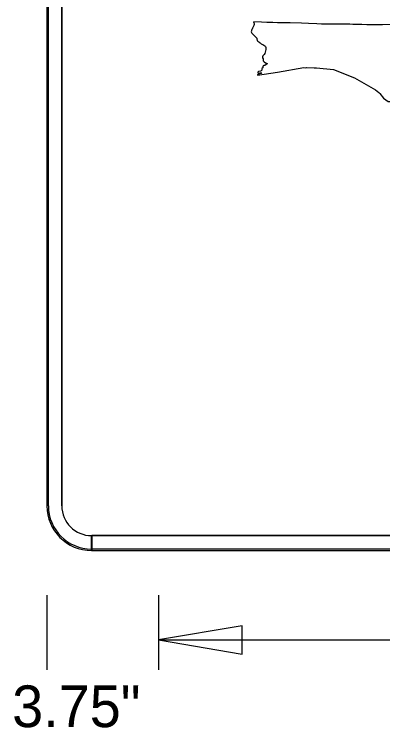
# Model space of a CAD drawing. Extents: x 0 to 770, y 0 to 495.
# Drawn here: x 108.2 to 139.1, y 37.8 to 97.6 of the extents above; entities that cross this region are included whole.
import ezdxf

# ---------------------------------------------------------------- set-up
doc = ezdxf.new("R2010")
doc.units = 0
for name, color, linetype in [('Dimension', 7, 'Continuous'), ('GSBWFill', 7, 'Continuous'), ('GSColorFill', 7, 'Continuous'), ('GSDims', 7, 'Continuous'), ('GSOutline', 7, 'Continuous'), ('SupstrConc', 7, 'Continuous')]:
    doc.layers.add(name, color=color, linetype=linetype)

msp = doc.modelspace()

# ---------------------------------------------------------------- linework, layer by layer
at = {"layer": 'Dimension'}
msp.add_lwpolyline([(120.294, 45.123), (127.31, 43.934), (127.31, 46.311)], close=True, dxfattribs=at)
at = {"layer": 'GSBWFill'}
for p, q in [((110.919, 138.873), (110.919, 56.373)), ((112.169, 56.373), (112.169, 138.873)), ((114.669, 52.623), (114.669, 53.873)), ((182.169, 53.873), (114.681, 53.873)), ((114.681, 53.873), (114.681, 52.623)), ((114.681, 52.623), (182.169, 52.623))]:
    msp.add_line(p, q, dxfattribs=at)
for radius in [3.75, 2.5]:
    msp.add_arc((114.669, 56.373), radius, 180, 270, dxfattribs=at)
at = {"layer": 'GSColorFill'}
for p, q in [((110.919, 138.873), (110.919, 56.373)), ((110.919, 138.873), (110.919, 56.373)), ((110.919, 138.873), (110.919, 56.373)), ((111.044, 56.373), (111.044, 138.873)), ((112.169, 56.373), (112.169, 138.873)), ((114.669, 52.623), (114.669, 53.873)), ((182.169, 53.873), (114.681, 53.873)), ((114.681, 53.873), (114.681, 52.623)), ((114.669, 52.623), (114.669, 52.748)), ((182.169, 52.748), (114.67, 52.748)), ((114.67, 52.748), (114.67, 52.623)), ((114.669, 52.623), (182.169, 52.623)), ((114.67, 52.623), (182.169, 52.623)), ((114.681, 52.623), (182.169, 52.623))]:
    msp.add_line(p, q, dxfattribs=at)
for radius in [3.75, 3.75, 3.75, 3.625, 2.5]:
    msp.add_arc((114.669, 56.373), radius, 180, 270, dxfattribs=at)
at = {"layer": 'GSDims'}
for p, q in [((110.918, 48.873), (110.918, 42.623)), ((120.294, 48.873), (120.294, 42.623)), ((120.294, 48.873), (120.294, 42.623)), ((120.294, 45.123), (176.544, 45.123))]:
    msp.add_line(p, q, dxfattribs=at)
at = {"layer": 'GSOutline'}
for p, q in [((110.919, 138.873), (110.919, 56.373)), ((112.169, 138.873), (112.169, 56.373)), ((114.669, 53.873), (182.169, 53.873)), ((114.669, 52.623), (182.169, 52.623))]:
    msp.add_line(p, q, dxfattribs=at)
for radius in [3.75, 2.5]:
    msp.add_arc((114.669, 56.373), radius, 180, 270, dxfattribs=at)
at = {"layer": 'SupstrConc'}
for p, q in [((130.272, 92.776), (132.459, 93.142)), ((128.58, 92.521), (130.272, 92.776))]:
    msp.add_line(p, q, dxfattribs=at)
for points in [[(128.252, 96.98), (128.288, 96.91), (128.299, 96.839), (128.299, 96.751), (128.288, 96.669), (128.235, 96.581), (128.17, 96.47), (128.123, 96.306), (128.082, 96.277), (128.071, 96.236), (128.053, 96.16), (128.082, 96.101), (128.123, 96.031), (128.358, 95.779), (128.411, 95.738), (128.493, 95.656), (128.522, 95.609), (128.522, 95.568), (128.534, 95.538), (128.534, 95.521), (128.551, 95.48), (128.563, 95.41), (128.58, 95.386), (128.622, 95.357), (128.692, 95.316), (128.715, 95.286), (128.774, 95.228), (128.815, 95.216), (128.85, 95.204), (128.891, 95.146), (128.95, 95.117), (129.02, 95.093), (129.043, 95.058), (129.114, 95.029), (129.196, 94.988), (129.254, 94.906), (129.284, 94.847), (129.295, 94.765), (129.295, 94.665), (129.196, 94.337), (129.155, 94.255), (129.102, 94.197), (129.032, 94.132), (129.002, 94.044), (129.002, 93.962), (129.061, 93.874), (129.061, 93.833), (129.061, 93.775), (129.073, 93.704), (129.143, 93.634), (129.266, 93.552), (129.354, 93.523), (129.401, 93.494), (129.401, 93.47), (129.213, 93.324), (129.155, 93.324), (129.114, 93.324), (129.073, 93.306), (129.032, 93.224), (129.02, 93.183), (129.02, 93.124), (128.95, 93.072), (128.95, 93.042), (128.961, 92.96), (128.95, 92.919), (128.903, 92.872), (128.85, 92.861), (128.704, 92.831), (128.663, 92.808), (128.622, 92.755), (128.622, 92.732), (128.651, 92.702), (128.745, 92.673), (128.815, 92.702), (128.95, 92.702), (128.92, 92.673), (128.879, 92.644), (128.762, 92.62), (128.692, 92.603), (128.58, 92.574), (128.58, 92.521)], [(139.702, 96.751), (139.081, 96.734), (138.325, 96.734), (137.75, 96.734), (137.323, 96.751), (136.59, 96.763), (136.338, 96.786), (135.395, 96.786), (134.563, 96.798), (133.942, 96.798), (133.549, 96.81), (132.87, 96.839), (132.278, 96.869), (131.317, 96.898), (130.807, 96.91), (130.256, 96.91), (129.875, 96.921), (129.377, 96.939), (128.932, 96.951), (128.252, 96.98)], [(132.459, 93.142), (132.612, 93.124), (132.682, 93.165), (133.332, 93.124), (133.532, 93.124), (134.958, 92.982)], [(134.958, 92.982), (136.731, 92.298), (137.692, 91.73), (138.477, 91.285)], [(138.477, 91.285), (138.764, 91.05), (138.834, 90.98), (139.151, 90.587), (139.538, 90.306), (139.655, 90.306), (139.895, 90.206), (140.036, 90.066)]]:
    msp.add_lwpolyline(points, dxfattribs=at)

# ---------------------------------------------------------------- texts
at = {"layer": 'GSDims'}
msp.add_text('3.75"', height=3.5, dxfattribs=at).set_placement((108.006, 37.804))

doc.saveas('drawing.dxf')
